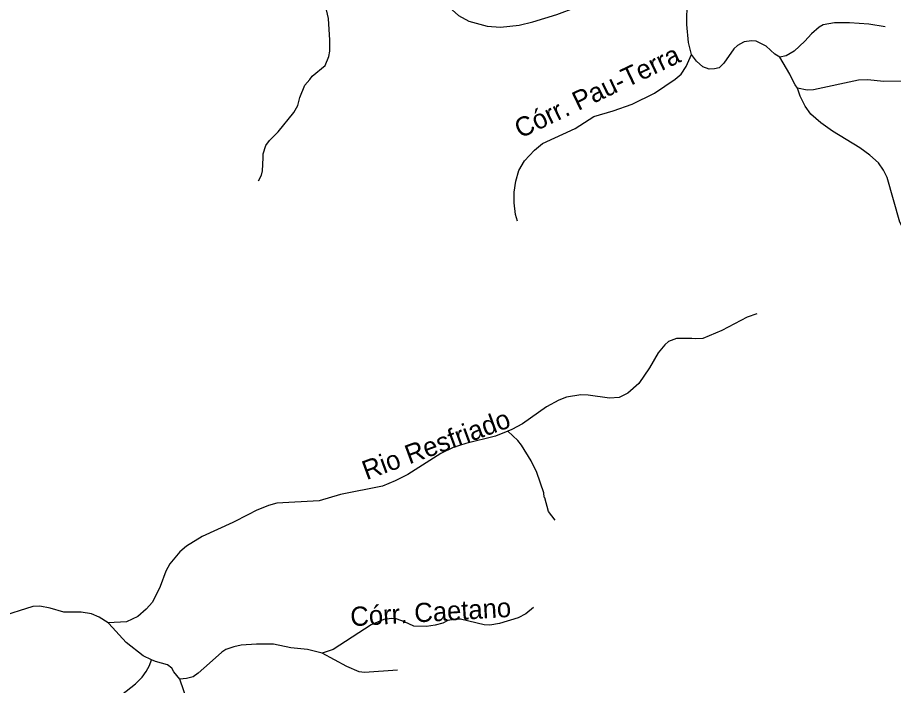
# Model space of a CAD drawing. Extents: x 280.4 to 335.6, y 8893.9 to 8949.5.
# Drawn here: x 296.28 to 303.6, y 8923.61 to 8929.19 of the extents above; entities that cross this region are included whole.
import ezdxf
from ezdxf.enums import TextEntityAlignment as Align

# ---------------------------------------------------------------- set-up
doc = ezdxf.new("R2010")
doc.units = 0
doc.header["$LTSCALE"] = 0.064
doc.layers.add('61', color=7, linetype='Continuous')
doc.layers.add('7', color=7, linetype='Continuous', lineweight=25)

msp = doc.modelspace()

# ---------------------------------------------------------------- linework, layer by layer
at = {"layer": '7'}
for points in [[(298.2945, 8927.823), (298.3192, 8927.8695), (298.3269, 8927.9054), (298.333, 8928.0138), (298.3349, 8928.0482), (298.3557, 8928.1187), (298.3869, 8928.1596), (298.4584, 8928.2313), (298.5903, 8928.392), (298.6223, 8928.4511), (298.6388, 8928.5188), (298.6818, 8928.6202), (298.7221, 8928.6694), (298.7438, 8928.6959), (298.851, 8928.7842), (298.8823, 8928.8599), (298.8913, 8928.9065), (298.8914, 8928.9962), (298.8786, 8929.1771), (298.8422, 8929.337), (298.8247, 8929.4475), (298.7573, 8929.6919), (298.72, 8929.8589), (298.6965, 8930.0094)], [(299.7324, 8929.7112), (299.7437, 8929.679), (299.7679, 8929.5449), (299.8057, 8929.4127), (299.8431, 8929.3328), (299.8856, 8929.2727), (299.9658, 8929.2041), (300.0506, 8929.1549), (300.205, 8929.1133), (300.3156, 8929.1043), (300.47, 8929.1231), (300.5858, 8929.1496), (300.7864, 8929.2102), (300.9491, 8929.2713), (300.9508, 8929.2718)], [(301.9102, 8928.8787), (301.885, 8928.9779), (301.8693, 8929.129), (301.8724, 8929.3216), (301.8501, 8929.5111), (301.8563, 8929.6312), (301.8606, 8929.6483)], [(303.5268, 8929.1097), (303.3911, 8929.1313), (303.2275, 8929.141), (303.1025, 8929.1408), (303.008, 8929.1239), (302.9763, 8929.106), (302.912, 8929.0512), (302.8563, 8928.9879), (302.7669, 8928.9046), (302.7008, 8928.866), (302.6462, 8928.8555)], [(302.6462, 8928.8555), (302.6065, 8928.8801), (302.5322, 8928.9478), (302.4498, 8928.9883), (302.4105, 8928.9921), (302.3491, 8928.984), (302.3423, 8928.9802), (302.2941, 8928.9533), (302.2623, 8928.9243), (302.1794, 8928.8051), (302.1416, 8928.7668), (302.1022, 8928.7569), (302.0572, 8928.7558), (302.0052, 8928.7733), (301.9508, 8928.8211), (301.9102, 8928.8787)], [(300.4565, 8927.4866), (300.4406, 8927.5423), (300.4284, 8927.6392), (300.43, 8927.7287), (300.4428, 8927.8183), (300.4684, 8927.9079), (300.5163, 8927.9894), (300.5999, 8928.0795), (300.6651, 8928.1343), (300.939, 8928.2601), (301.0945, 8928.3601), (301.2558, 8928.4071), (301.415, 8928.4629), (301.6015, 8928.5553), (301.773, 8928.6701), (301.8223, 8928.7134), (301.8652, 8928.7763), (301.9102, 8928.8787)], [(302.7931, 8928.5951), (302.7745, 8928.625), (302.752, 8928.6669), (302.7316, 8928.7132), (302.6462, 8928.8555)], [(304.1178, 8928.8336), (304.0916, 8928.8196), (304.0537, 8928.7828), (303.954, 8928.7209), (303.8904, 8928.6919), (303.8767, 8928.6927), (303.8011, 8928.6692), (303.7051, 8928.6548), (303.5139, 8928.6532), (303.3789, 8928.6659), (303.3038, 8928.6626), (302.9284, 8928.5824), (302.8743, 8928.5796), (302.7931, 8928.5951)], [(303.9201, 8927.1806), (303.8872, 8927.2161), (303.757, 8927.3141), (303.7132, 8927.3554), (303.6494, 8927.4786), (303.5433, 8927.851), (303.5132, 8927.9111), (303.4703, 8927.9716), (303.3991, 8928.0379), (303.3143, 8928.0986), (303.0856, 8928.2362), (302.9882, 8928.3066), (302.9045, 8928.3791), (302.8576, 8928.4452), (302.8172, 8928.529), (302.7931, 8928.5951)], [(302.4539, 8926.7122), (302.3754, 8926.6833), (302.1625, 8926.5721), (302.0053, 8926.5052), (301.942, 8926.5023), (301.9118, 8926.507), (301.7843, 8926.5054), (301.7185, 8926.4808), (301.6859, 8926.4529), (301.6326, 8926.3854), (301.5586, 8926.2617), (301.4688, 8926.1308), (301.3776, 8926.0492), (301.3057, 8926.0144), (301.2256, 8926.008), (301.0458, 8926.0336), (300.9854, 8926.0368), (300.8663, 8926.016), (300.8025, 8925.9911), (300.6981, 8925.9345), (300.5001, 8925.7946), (300.4106, 8925.745), (300.3764, 8925.7312)], [(300.3764, 8925.7312), (300.2738, 8925.69), (300.0268, 8925.6289), (299.9206, 8925.595), (299.8158, 8925.5458), (299.5414, 8925.3702), (299.4367, 8925.3179), (299.3296, 8925.274), (298.9785, 8925.2021), (298.8026, 8925.1509), (298.4483, 8925.1296), (298.3789, 8925.1121), (298.2741, 8925.0692), (298.2126, 8925.0375), (298.0796, 8924.9688), (297.8237, 8924.8521), (297.6945, 8924.7728), (297.6376, 8924.7237), (297.5557, 8924.6256), (297.5212, 8924.5629), (297.4744, 8924.4343), (297.4109, 8924.3049), (297.3583, 8924.2446), (297.2863, 8924.1848), (297.1936, 8924.1404), (297.0395, 8924.1308)], [(300.7702, 8924.989), (300.7147, 8925.0603), (300.6862, 8925.1744), (300.6797, 8925.18), (300.6759, 8925.2178), (300.6172, 8925.3867), (300.5719, 8925.4841), (300.4895, 8925.616), (300.4602, 8925.6529), (300.3764, 8925.7312)], [(297.0395, 8924.1308), (296.9651, 8924.1788), (296.9004, 8924.2061), (296.8155, 8924.22), (296.6709, 8924.2202), (296.5557, 8924.2552), (296.4694, 8924.2711), (296.4098, 8924.2672), (296.1274, 8924.179), (296.0411, 8924.1659), (295.9807, 8924.1641), (295.9203, 8924.1762), (295.6776, 8924.2792), (295.6001, 8924.3271), (295.4696, 8924.3892), (295.405, 8924.4023), (295.3394, 8924.4037), (295.2755, 8924.3919), (295.2451, 8924.3766), (295.1952, 8924.3347)], [(300.5895, 8924.2595), (300.5256, 8924.207), (300.4618, 8924.1737), (300.3069, 8924.1252), (300.2259, 8924.113), (300.1788, 8924.1148), (299.9818, 8924.1618), (299.9437, 8924.1624), (299.875, 8924.15), (299.8333, 8924.1302), (299.7685, 8924.1114), (299.6967, 8924.1), (299.5912, 8924.1037), (299.5135, 8924.1407), (299.4447, 8924.164), (299.4088, 8924.1687), (299.3421, 8924.1598), (299.2343, 8924.1148), (298.9169, 8923.9098), (298.8277, 8923.8795)], [(297.4006, 8923.8241), (297.3334, 8923.856), (297.1892, 8923.9679), (297.0455, 8924.1269), (297.0395, 8924.1308)], [(298.8277, 8923.8795), (298.7026, 8923.9081), (298.5636, 8923.9239), (298.4212, 8923.9529), (298.2787, 8923.9544), (298.1501, 8923.9449), (298.0882, 8923.9327), (298.0221, 8923.9084), (297.9888, 8923.8868), (297.8869, 8923.7963), (297.7908, 8923.711), (297.7505, 8923.6817), (297.6944, 8923.6665), (297.6381, 8923.66)], [(299.4559, 8923.7366), (299.1786, 8923.718), (299.1351, 8923.7228), (299.0325, 8923.7673), (298.8277, 8923.8795)], [(296.6498, 8922.9222), (296.7088, 8923.0187), (296.7132, 8923.0372), (296.7103, 8923.0909), (296.7327, 8923.2034), (296.7552, 8923.2417), (296.7954, 8923.2814), (296.9212, 8923.3423), (297.0378, 8923.4207), (297.1509, 8923.5303), (297.2681, 8923.6219), (297.3237, 8923.6789), (297.3585, 8923.7255), (297.3848, 8923.7754), (297.4006, 8923.8241)], [(297.6381, 8923.66), (297.5878, 8923.7232), (297.5716, 8923.7536), (297.534, 8923.7815), (297.4343, 8923.8081), (297.4006, 8923.8241)], [(297.7973, 8923.1706), (297.7696, 8923.2947), (297.7589, 8923.3091), (297.7076, 8923.4581), (297.6381, 8923.66)]]:
    msp.add_lwpolyline(points, dxfattribs=at)

# ---------------------------------------------------------------- texts
at = {"layer": '61'}
for s, rotation, p in [('Córr. Pau-Terra', 25.56, (301.1562, 8928.497)), ('Rio Resfriado', 20.225, (299.8045, 8925.5465)), ('Córr. Caetano', 3.366, (299.7367, 8924.1424))]:
    msp.add_text(s, height=0.16, rotation=rotation, dxfattribs=at).set_placement(p, align=Align.CENTER)

doc.saveas('drawing.dxf')
